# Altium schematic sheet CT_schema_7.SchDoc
size 479 x 328 mm
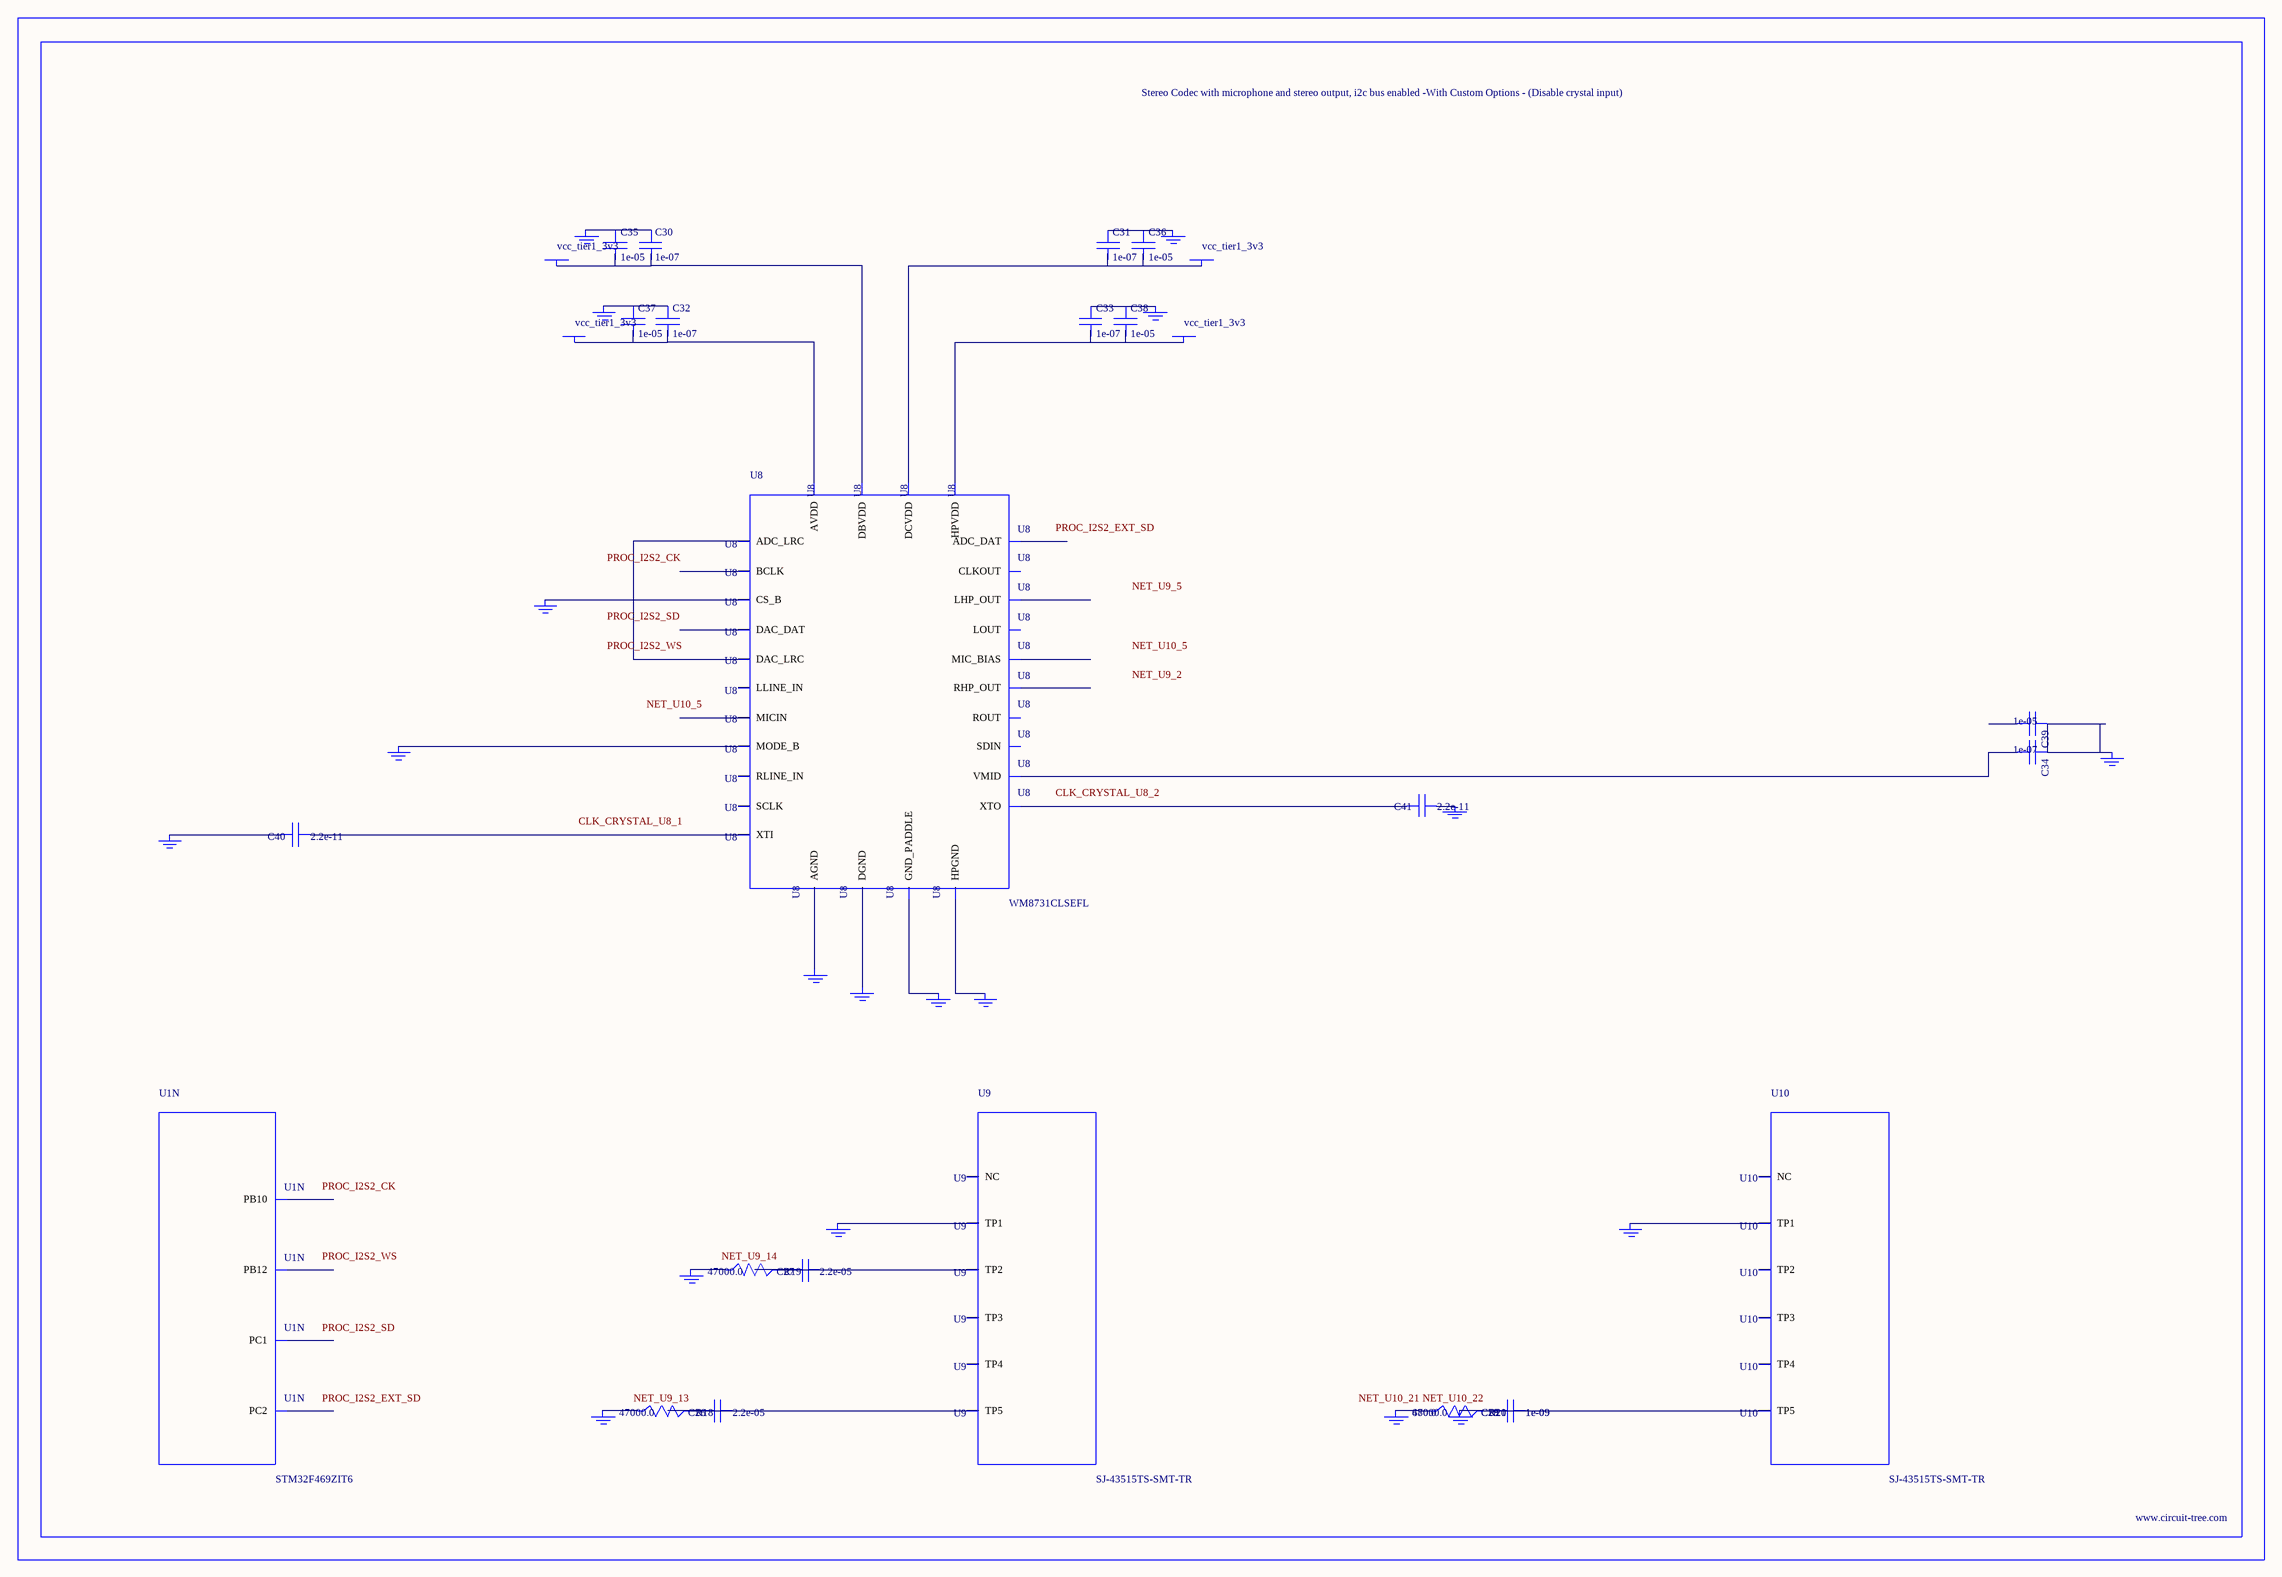
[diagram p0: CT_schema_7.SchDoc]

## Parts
BORDER6  (no value)
C26  2.2e-05  [C1210]
C27  2.2e-05  [C1210]
C28  1e-09  [C0402]
C29  1e-09  [C0402]
C30  1e-07  [C0402]
C31  1e-07  [C0402]
C32  1e-07  [C0402]
C33  1e-07  [C0402]
C34  1e-07  [C0402]
C35  1e-05  [C0805]
C36  1e-05  [C0805]
C37  1e-05  [C0805]
C38  1e-05  [C0805]
C39  1e-05  [C0805]
C40  2.2e-11  [C0402]
C41  2.2e-11  [C0402]
GND_INSTANCE_6_0  (no value)
GND_INSTANCE_6_1  (no value)
GND_INSTANCE_6_2  (no value)
GND_INSTANCE_6_3  (no value)
GND_INSTANCE_6_4  (no value)
GND_INSTANCE_6_5  (no value)
GND_INSTANCE_6_6  (no value)
GND_INSTANCE_6_7  (no value)
GND_INSTANCE_6_8  (no value)
GND_INSTANCE_6_9  (no value)
GND_INSTANCE_6_10  (no value)
GND_INSTANCE_6_11  (no value)
GND_INSTANCE_6_12  (no value)
GND_INSTANCE_6_13  (no value)
GND_INSTANCE_6_14  (no value)
GND_INSTANCE_6_15  (no value)
GND_INSTANCE_6_16  (no value)
GND_INSTANCE_6_17  (no value)
GND_INSTANCE_6_18  (no value)
POWER_INSTANCE_6_0  vcc_tier1_3v3
POWER_INSTANCE_6_1  vcc_tier1_3v3
POWER_INSTANCE_6_2  vcc_tier1_3v3
POWER_INSTANCE_6_3  vcc_tier1_3v3
R18  47000.0  [R0603]
R19  47000.0  [R0603]
R20  47000.0  [R0603]
R21  680.0  [R0603]
U1  STM32F469ZIT6  [LQFP144]  (part N of 14)
U8  WM8731CLSEFL  [QFN-28]
U9  SJ-43515TS-SMT-TR  [SJ-43515TS-SMT-TR]
U10  SJ-43515TS-SMT-TR  [SJ-43515TS-SMT-TR]

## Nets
NetC26_1: C26.1 C26.2 R18.2 U9.5(TP5)
NetC27_1: C27.1 C27.2 R19.2 U9.2(TP2)
NetC28_1: C28.1 C28.2 C29.1 C29.2 GND_INSTANCE_6_18.0(GND) R20.2 R21.2 U10.5(TP5)
NetC30_1: C30.1 C35.1 GND_INSTANCE_6_3.0(GND)
NetC30_2: C30.2 C35.2 POWER_INSTANCE_6_1.0(PWR) U8.5(DBVDD)
NetC31_1: C31.1 C36.1 GND_INSTANCE_6_2.0(GND)
NetC31_2: C31.2 C36.2 POWER_INSTANCE_6_0.0(PWR) U8.3(DCVDD)
NetC32_1: C32.1 C37.1 GND_INSTANCE_6_6.0(GND)
NetC32_2: C32.2 C37.2 POWER_INSTANCE_6_3.0(PWR) U8.18(AVDD)
NetC33_1: C33.1 C38.1 GND_INSTANCE_6_4.0(GND)
NetC33_2: C33.2 C38.2 POWER_INSTANCE_6_2.0(PWR) U8.12(HPVDD)
NetC34_1: C34.1 C39.1 GND_INSTANCE_6_7.0(GND)
NetC34_2: C34.2 U8.20(VMID)
NetC40_1: C40.1 U8.1(XTI)
NetC40_2: C40.2 GND_INSTANCE_6_0.0(GND)
NetC41_1: C41.1 GND_INSTANCE_6_1.0(GND)
NetC41_2: C41.2 U8.2(XTO)
NetGND_INSTANCE_6_5_0: GND_INSTANCE_6_5.0(GND) U8.15(HPGND)
NetGND_INSTANCE_6_8_0: GND_INSTANCE_6_8.0(GND) U8.25(MODE_B)
NetGND_INSTANCE_6_9_0: GND_INSTANCE_6_9.0(GND) U8.26(CS_B)
NetGND_INSTANCE_6_10_0: GND_INSTANCE_6_10.0(GND) U8.29(GND_PADDLE)
NetGND_INSTANCE_6_11_0: GND_INSTANCE_6_11.0(GND) U8.4(DGND)
NetGND_INSTANCE_6_12_0: GND_INSTANCE_6_12.0(GND) U8.19(AGND)
NetGND_INSTANCE_6_13_0: GND_INSTANCE_6_13.0(GND) U9.1(TP1)
NetGND_INSTANCE_6_14_0: GND_INSTANCE_6_14.0(GND) R19.1
NetGND_INSTANCE_6_15_0: GND_INSTANCE_6_15.0(GND) R18.1
NetGND_INSTANCE_6_16_0: GND_INSTANCE_6_16.0(GND) U10.1(TP1)
NetGND_INSTANCE_6_17_0: GND_INSTANCE_6_17.0(GND) R20.1 R21.1
NetU8_9: U8.9(DAC_LRC) U8.11(ADC_LRC)

Not connected (* = marked no-connect by the designer): C39 2; U1 22(PC1) 23(PC2) 63(PB10) 67(PB12); U8 6(CLKOUT) 7(BCLK) 8(DAC_DAT) 10(ADC_DAT) 13(LHP_OUT) 14(RHP_OUT) 16(LOUT) 17(ROUT) 21(MIC_BIAS) 22(MICIN) 23(RLINE_IN) 24(LLINE_IN) 27(SDIN) 28(SCLK); U9 3(TP3) 4(TP4) 6(NC); U10 2(TP2) 3(TP3) 4(TP4) 6(NC)

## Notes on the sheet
- Labels drawn without touching a wire or pin: CLK_CRYSTAL_U8_1, CLK_CRYSTAL_U8_2, NET_U9_2, NET_U9_5, NET_U9_13, NET_U9_14, NET_U10_5, NET_U10_21, NET_U10_22, PROC_I2S2_CK, PROC_I2S2_EXT_SD, PROC_I2S2_SD, PROC_I2S2_WS

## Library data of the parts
BORDER6 = BORDER_PAGE6
C26 C27 = C1210C224K5RACTU
C28 C29 = C0402C102K3RAC
C30-C34 = C0402C104K3RACTU
C35-C39 = C0805C106K8RACTU
C40 C41 = C0402C220K3RAC
GND_INSTANCE_6_0-GND_INSTANCE_6_18 = GND
POWER_INSTANCE_6_0-POWER_INSTANCE_6_3 = PWR
R18-R20 = RC0603JR-0747KL
R21 = RC0603JR-07680RL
